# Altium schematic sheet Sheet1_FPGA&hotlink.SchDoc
size A3
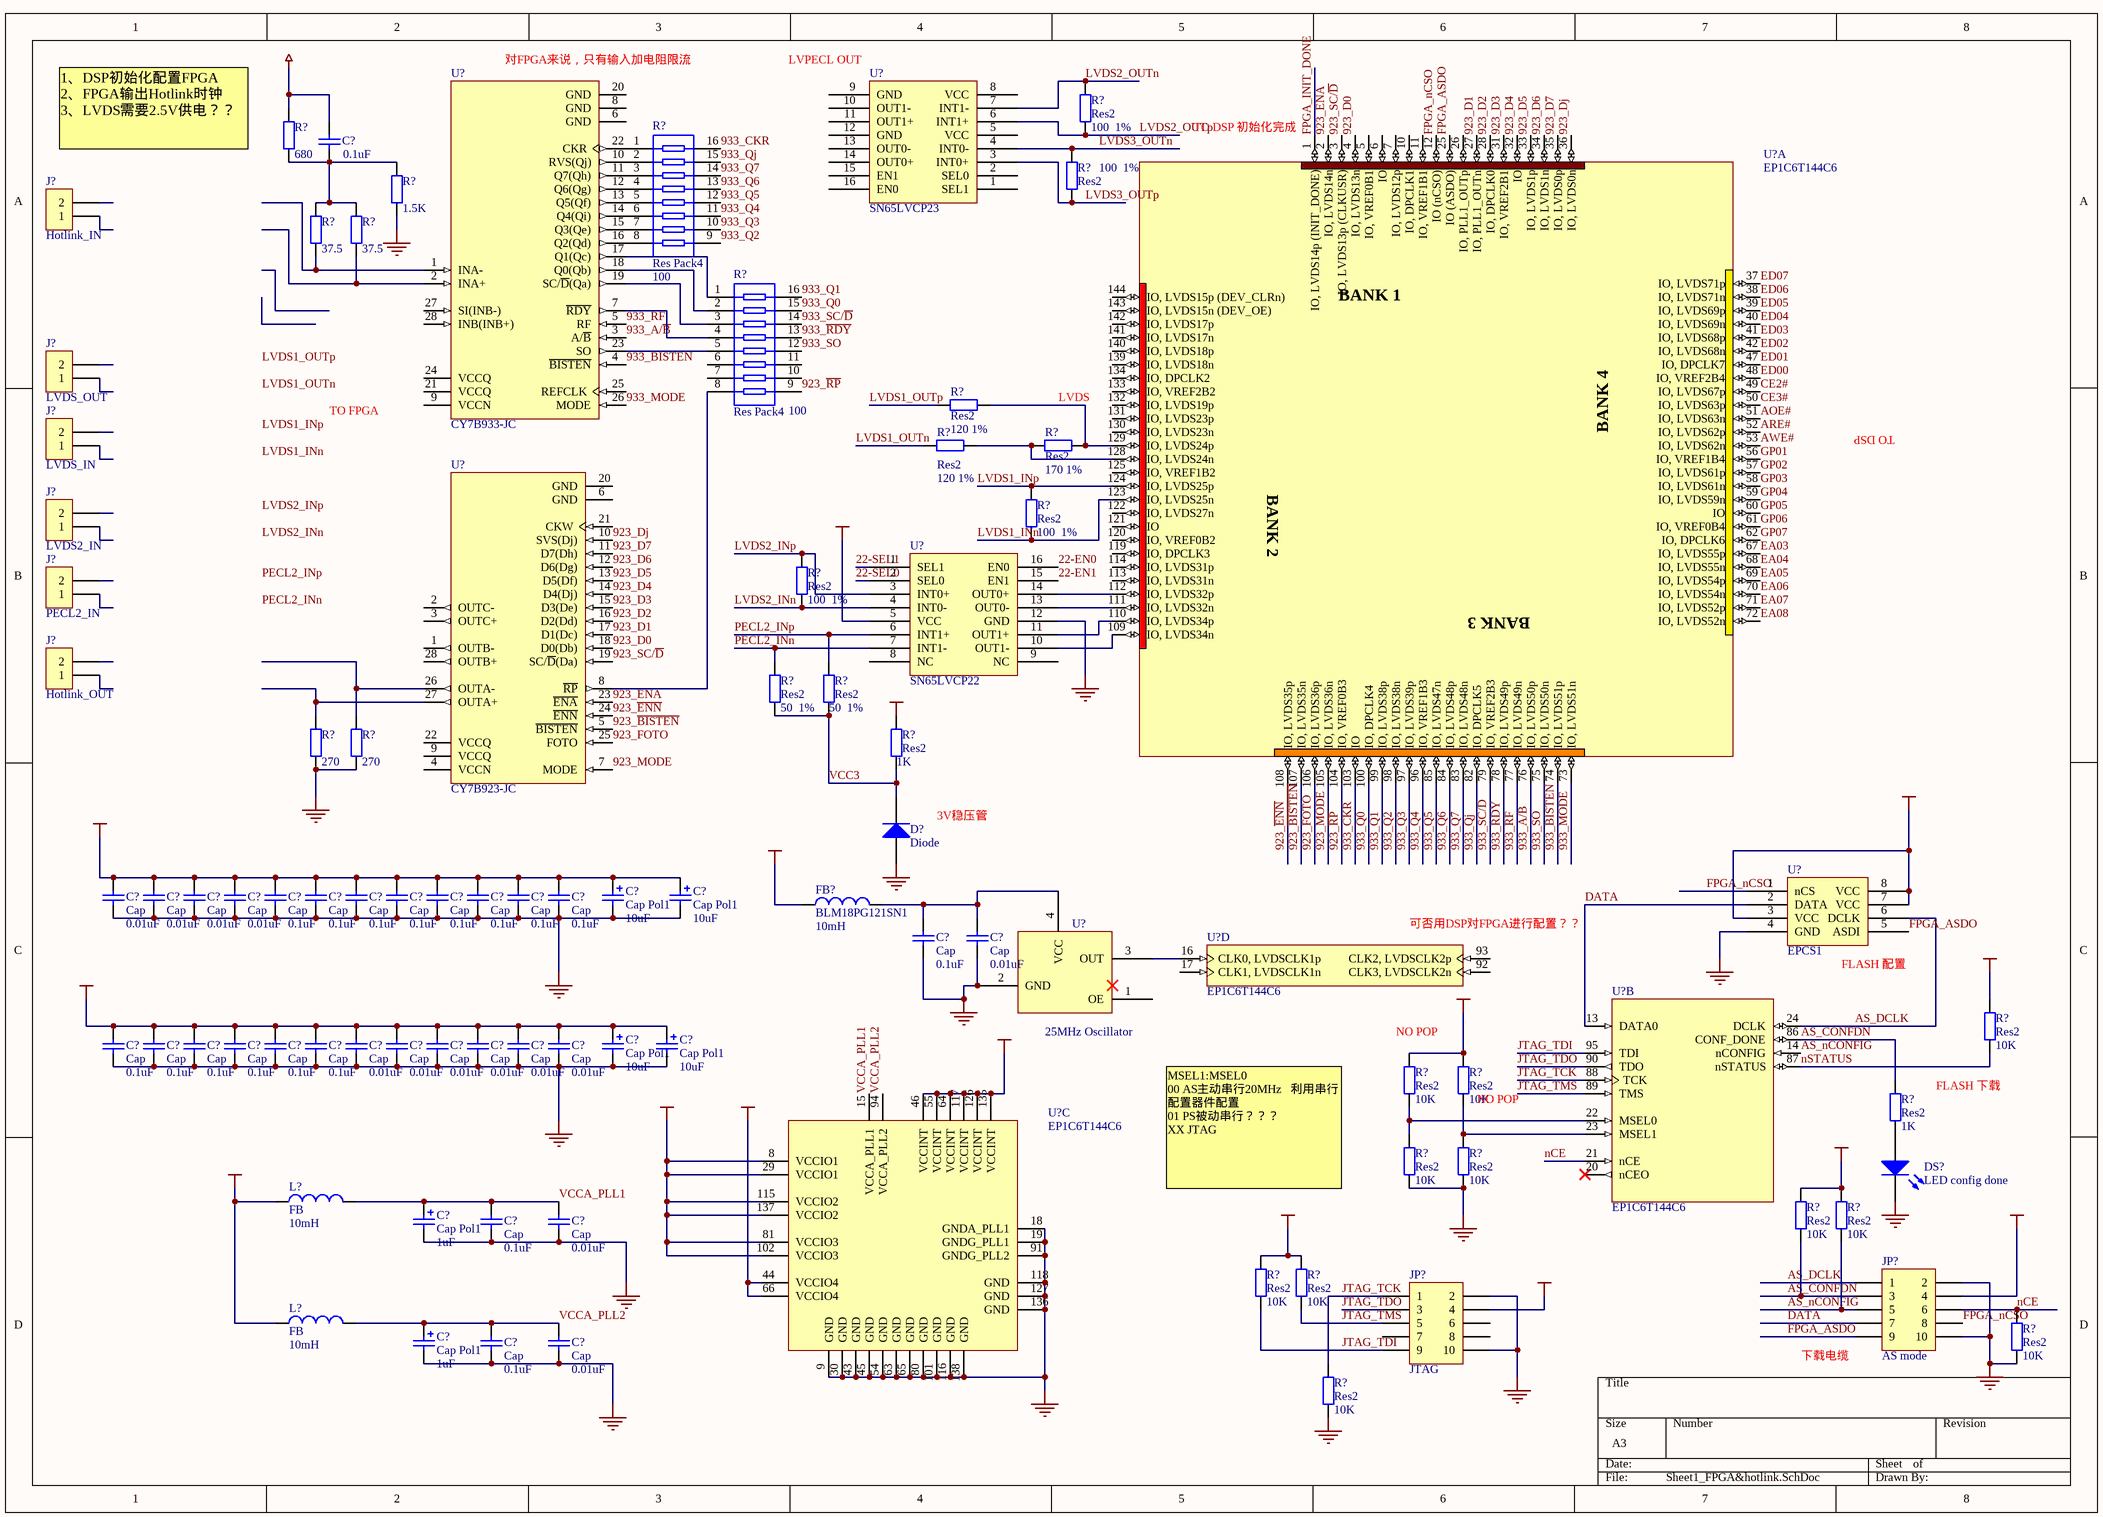
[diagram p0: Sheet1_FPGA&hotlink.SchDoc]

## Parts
(Parts that share a designator on the sheet are numbered #1, #2 ... from top to bottom, then left to right.)
C?#1  value 0.1uF  [RAD-0.3]
C?#2  Cap Pol1  value 10uF  [CC3216-1206]
C?#3  Cap Pol1  value 10uF  [CC3216-1206]
C?#4  Cap  value 0.01uF  [C1608-0603]
C?#5  Cap  value 0.01uF  [C1608-0603]
C?#6  Cap  value 0.01uF  [C1608-0603]
C?#7  Cap  value 0.01uF  [C1608-0603]
C?#8  Cap  value 0.1uF  [C1608-0603]
C?#9  Cap  value 0.1uF  [C1608-0603]
C?#10  Cap  value 0.1uF  [C1608-0603]
C?#11  Cap  value 0.1uF  [C1608-0603]
C?#12  Cap  value 0.1uF  [C1608-0603]
C?#13  Cap  value 0.1uF  [C1608-0603]
C?#14  Cap  value 0.1uF  [C1608-0603]
C?#15  Cap  value 0.1uF  [C1608-0603]
C?#16  Cap  value 0.1uF  [C1608-0603]
C?#17  Cap  value 0.01uF  [C1608-0603]
C?#18  Cap Pol1  value 10uF  [CC3216-1206]
C?#19  Cap Pol1  value 10uF  [CC3216-1206]
C?#20  Cap  value 0.1uF  [C1608-0603]
C?#21  Cap  value 0.1uF  [C1608-0603]
C?#22  Cap  value 0.1uF  [C1608-0603]
C?#23  Cap  value 0.1uF  [C1608-0603]
C?#24  Cap  value 0.1uF  [C1608-0603]
C?#25  Cap  value 0.1uF  [C1608-0603]
C?#26  Cap  value 0.01uF  [C1608-0603]
C?#27  Cap  value 0.01uF  [C1608-0603]
C?#28  Cap  value 0.01uF  [C1608-0603]
C?#29  Cap  value 0.01uF  [C1608-0603]
C?#30  Cap  value 0.01uF  [C1608-0603]
C?#31  Cap  value 0.01uF  [C1608-0603]
C?#32  Cap Pol1  value 1uF  [C1608-0603]
C?#33  Cap  value 0.1uF  [C1608-0603]
C?#34  Cap  value 0.01uF  [C1608-0603]
C?#35  Cap Pol1  value 1uF  [C1608-0603]
C?#36  Cap  value 0.1uF  [C1608-0603]
C?#37  Cap  value 0.01uF  [C1608-0603]
D?  Diode  [DSO-C2/X3.3]
DS?  LED config done  [SMD _LED]
FB?  BLM18PG121SN1  value 10mH  [C1608-0603]
J?#1  Hotlink_IN  [SMA]
J?#2  LVDS_OUT  [SMA]
J?#3  LVDS_IN  [SMA]
J?#4  LVDS2_IN  [SMA]
J?#5  PECL2_IN  [SMA]
J?#6  Hotlink_OUT  [SMA]
JP?#1  AS mode  [HDR2X5]
JP?#2  JTAG  [HDR2X5]
L?#1  FB  value 10mH  [C1608-0603]
L?#2  FB  value 10mH  [C1608-0603]
R?#1  680  [CR1608-0603]
R?#2  Res2  value 100  1%  [CR1608-0603]
R?#3  Res Pack4  value 100  [SSO-G16/X.4]
R?#4  1.5K  [CR1608-0603]
R?#5  Res2  value 100  1%  [CR1608-0603]
R?#6  value 37.5  [CR1608-0603]  (hidden comment: 1.5K)
R?#7  value 37.5  [CR1608-0603]  (hidden comment: 1.5K)
R?#8  Res Pack4  value 100  [SSO-G16/X.4]
R?#9  Res2  value 120 1%  [CR1608-0603]
R?#10  Res2  value 120 1%  [CR1608-0603]
R?#11  Res2  value 170 1%  [CR1608-0603]
R?#12  Res2  value 100  1%  [CR1608-0603]
R?#13  Res2  value 100  1%  [CR1608-0603]
R?#14  Res2  value 50  1%  [CR1608-0603]
R?#15  Res2  value 50  1%  [CR1608-0603]
R?#16  value 270  [CR1608-0603]  (hidden comment: 1.5K)
R?#17  value 270  [CR1608-0603]  (hidden comment: 1.5K)
R?#18  Res2  value 1K  [CR1608-0603]
R?#19  Res2  value 10K  [CR1608-0603]
R?#20  Res2  value 10K  [CR1608-0603]
R?#21  Res2  value 10K  [CR1608-0603]
R?#22  Res2  value 1K  [CR1608-0603]
R?#23  Res2  value 10K  [CR1608-0603]
R?#24  Res2  value 10K  [CR1608-0603]
R?#25  Res2  value 10K  [CR1608-0603]
R?#26  Res2  value 10K  [CR1608-0603]
R?#27  Res2  value 10K  [CR1608-0603]
R?#28  Res2  value 10K  [CR1608-0603]
R?#29  Res2  value 10K  [CR1608-0603]
R?#30  Res2  value 10K  [CR1608-0603]
U?#1  SN65LVCP23
U?#2  CY7B933-JC  [J64]
U?#3  SN65LVCP22  [Model Name]
U?#4  EP1C6T144C6  [TQFP144]  (part A of 4)
U?#5  CY7B923-JC  [J64]
U?#6  EPCS1  [SO-G8]
U?#7  25MHz Oscillator  [OSC50MHz]
U?#8  EP1C6T144C6  [TQFP144]  (part D of 4)
U?#9  EP1C6T144C6  [TQFP144]  (part B of 4)
U?#10  EP1C6T144C6  [TQFP144]  (part C of 4)

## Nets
+5V: C?#1.2 R?#1.1
GND: C?#2.2 C?#3.2 C?#4.1 C?#5.1 C?#6.1 C?#7.1 C?#8.1 C?#9.1 C?#10.1 C?#11.1 C?#12.1 C?#13.1 C?#14.1 C?#15.1 C?#16.1 C?#17.1 C?#18.2 C?#19.2 C?#20.1 C?#21.1 C?#22.1 C?#23.1 C?#24.1 C?#25.1 C?#26.1 C?#27.1 C?#28.1 C?#29.1 C?#30.1 C?#31.1 C?#32.2 C?#33.1 C?#34.1 C?#35.2 C?#36.1 C?#37.1 D?.1(A) DS?.2(K) JP?#1.2 JP?#1.10 JP?#2.2 JP?#2.10 R?#4.2 R?#16.2 R?#17.2 R?#23.1 R?#24.1 R?#29.1 R?#30.1 U?#3.12(GND) U?#6.4(GND) U?#7.2(GND) U?#10.9(GND) U?#10.18(GNDA_PLL1) U?#10.19(GNDG_PLL1) U?#10.30(GND) U?#10.43(GND) U?#10.45(GND) U?#10.54(GND) U?#10.63(GND) U?#10.65(GND) U?#10.80(GND) U?#10.91(GNDG_PLL2) U?#10.101(GND) U?#10.116(GND) U?#10.118(GND) U?#10.127(GND) U?#10.136(GND) U?#10.138(GND)
V3.3: FB?.1
VCC1.5: C?#18.1 C?#19.1 C?#20.2 C?#21.2 C?#22.2 C?#23.2 C?#24.2 C?#25.2 C?#26.2 C?#27.2 C?#28.2 C?#29.2 C?#30.2 C?#31.2 L?#1.1 L?#2.1 U?#10.46(VCCINT) U?#10.55(VCCINT) U?#10.64(VCCINT) U?#10.117(VCCINT) U?#10.126(VCCINT) U?#10.135(VCCINT)
VCC2.5: U?#10.44(VCCIO4) U?#10.66(VCCIO4)
VCC3.3: C?#2.1 C?#3.1 C?#4.2 C?#5.2 C?#6.2 C?#7.2 C?#8.2 C?#9.2 C?#10.2 C?#11.2 C?#12.2 C?#13.2 C?#14.2 C?#15.2 JP?#1.4 JP?#2.4 R?#19.2 R?#20.2 R?#21.2 R?#25.2 R?#26.2 R?#27.2 R?#28.2 U?#3.5(VCC) U?#6.3(VCC) U?#6.7(VCC) U?#6.8(VCC) U?#10.8(VCCIO1) U?#10.29(VCCIO1) U?#10.81(VCCIO3) U?#10.102(VCCIO3) U?#10.115(VCCIO2) U?#10.137(VCCIO2)
VCC5: R?#18.1
22-EN0: U?#3.16(EN0)
22-EN1: U?#3.15(EN1)
22-SEL0: U?#3.2(SEL0)
22-SEL1: U?#3.1(SEL1)
923_~{BISTEN}: U?#4.107(IO,_LVDS35n) U?#5.5(~{BISTEN})
923_D0: U?#4.4(IO,_LVDS13n) U?#5.18(D0(Db))
923_D1: U?#4.27(IO,_PLL1_OUTn) U?#5.17(D1(Dc))
923_D2: U?#4.28(IO,_DPCLK0) U?#5.16(D2(Dd))
923_D3: U?#4.31(IO,_VREF2B1) U?#5.15(D3(De))
923_D4: U?#4.32(IO) U?#5.14(D4(Dj))
923_D5: U?#4.33(IO,_LVDS1p) U?#5.13(D5(Df))
923_D6: U?#4.34(IO,_LVDS1n) U?#5.12(D6(Dg))
923_D7: U?#4.35(IO,_LVDS0p) U?#5.11(D7(Dh))
923_Dj: U?#4.36(IO,_LVDS0n) U?#5.10(SVS(Dj))
923_~{ENA}: U?#4.2(IO,_LVDS14n) U?#5.23(~{ENA})
923_~{ENN}: U?#4.108(IO,_LVDS35p) U?#5.24(~{ENN})
923_FOTO: U?#4.106(IO,_LVDS36p) U?#5.25(FOTO)
923_MODE: U?#4.105(IO,_LVDS36n) U?#5.7(MODE)
923_~{RP}: R?#8.9 U?#4.104(IO,_VREF0B3)
923_SC/~{D}: U?#4.3(IO,_LVDS13p_(CLKUSR)) U?#5.19(SC/~{D}(Da))
933_A/~{B}: U?#2.3(A/~{B}) U?#4.76(IO,_LVDS50p)
933_~{BISTEN}: U?#2.4(~{BISTEN}) U?#4.74(IO,_LVDS51p)
933_CKR: R?#3.16 U?#4.103(IO)
933_MODE: U?#2.26(MODE) U?#4.73(IO,_LVDS51n)
933_Q0: R?#8.15 U?#4.100(IO,_DPCLK4)
933_Q1: R?#8.16 U?#4.99(IO,_LVDS38p)
933_Q2: R?#3.9 U?#4.98(IO,_LVDS38n)
933_Q3: R?#3.10 U?#4.97(IO,_LVDS39p)
933_Q4: R?#3.11 U?#4.96(IO,_VREF1B3)
933_Q5: R?#3.12 U?#4.85(IO,_LVDS47n)
933_Q6: R?#3.13 U?#4.84(IO,_LVDS48p)
933_Q7: R?#3.14 U?#4.83(IO,_LVDS48n)
933_Qj: R?#3.15 U?#4.82(IO,_DPCLK5)
933_~{RDY}: R?#8.13 U?#4.78(IO,_LVDS49p)
933_RF: U?#2.5(RF) U?#4.77(IO,_LVDS49n)
933_SC/~{D}: R?#8.14 U?#4.79(IO,_VREF2B3)
933_SO: R?#8.12 U?#4.75(IO,_LVDS50n)
AOE#: U?#4.51(IO,_LVDS63n)
ARE#: U?#4.52(IO,_LVDS62p)
AS_CONFDN: JP?#1.3 R?#22.2 R?#25.1 U?#9.86(CONF_DONE)
AS_DCLK: JP?#1.1 U?#6.6(DCLK) U?#9.24(DCLK)
AS_nCONFIG: JP?#1.5 R?#26.1 U?#9.14(nCONFIG)
AWE#: U?#4.53(IO,_LVDS62n)
CE2#: U?#4.49(IO,_LVDS67p)
CE3#: U?#4.50(IO,_LVDS63p)
DATA: JP?#1.7 U?#6.2(DATA) U?#9.13(DATA0)
EA03: U?#4.67(IO,_LVDS55p)
EA04: U?#4.68(IO,_LVDS55n)
EA05: U?#4.69(IO,_LVDS54p)
EA06: U?#4.70(IO,_LVDS54n)
EA07: U?#4.71(IO,_LVDS52p)
EA08: U?#4.72(IO,_LVDS52n)
ED00: U?#4.48(IO,_VREF2B4)
ED01: U?#4.47(IO,_DPCLK7)
ED02: U?#4.42(IO,_LVDS68n)
ED03: U?#4.41(IO,_LVDS68p)
ED04: U?#4.40(IO,_LVDS69n)
ED05: U?#4.39(IO,_LVDS69p)
ED06: U?#4.38(IO,_LVDS71n)
ED07: U?#4.37(IO,_LVDS71p)
FPGA_ASDO: JP?#1.9 U?#4.25(IO_(ASDO)) U?#6.5(ASDI)
FPGA_INIT_DONE: U?#4.1(IO,_LVDS14p_(INIT_DONE))
FPGA_nCSO: JP?#1.8 U?#4.12(IO_(nCSO)) U?#6.1(nCS)
GP01: U?#4.56(IO,_VREF1B4)
GP02: U?#4.57(IO,_LVDS61p)
GP03: U?#4.58(IO,_LVDS61n)
GP04: U?#4.59(IO,_LVDS59n)
GP05: U?#4.60(IO)
GP06: U?#4.61(IO,_VREF0B4)
GP07: U?#4.62(IO,_DPCLK6)
JTAG_TCK: JP?#2.1 R?#30.2 U?#9.88(TCK)
JTAG_TDI: JP?#2.9 R?#27.1 U?#9.95(TDI)
JTAG_TDO: JP?#2.3 U?#9.90(TDO)
JTAG_TMS: JP?#2.5 R?#28.1 U?#9.89(TMS)
LVDS1_INn: R?#12.2 U?#4.123(IO,_LVDS25n)
LVDS1_INp: R?#12.1 U?#4.124(IO,_LVDS25p)
LVDS1_OUTn: R?#10.1
LVDS1_OUTp: R?#9.1
LVDS2_INn: R?#13.2 U?#3.4(INT0-)
LVDS2_INp: R?#13.1 U?#3.3(INT0+)
LVDS2_OUTn: R?#2.2 U?#1.7(INT1-)
LVDS2_OUTp: R?#2.1 U?#1.6(INT1+)
LVDS3_OUTn: R?#5.2 U?#1.4(INT0-)
LVDS3_OUTp: R?#5.1 U?#1.3(INT0+)
nCE: JP?#1.6 R?#29.2 U?#9.21(nCE)
nSTATUS: R?#19.1 U?#9.87(nSTATUS)
PECL2_INn: R?#14.1 U?#3.7(INT1-)
PECL2_INp: R?#15.1 U?#3.6(INT1+)
VCC3: D?.2(K) R?#14.2 R?#15.2 R?#18.2
VCCA_PLL1: C?#32.1 C?#33.2 C?#34.2 L?#1.2 U?#10.15(VCCA_PLL1)
VCCA_PLL2: C?#35.1 C?#36.2 C?#37.2 L?#2.2 U?#10.94(VCCA_PLL2)
NetC?#1_1: C?#1.1 R?#1.2 R?#4.1 R?#6.1 R?#7.1
NetC?#16_2: C?#16.2 C?#17.2 FB?.2 U?#7.4(VCC)
NetDS?_1: DS?.1(A) R?#22.1
NetR?#3_1: R?#3.1 U?#2.22(CKR)
NetR?#3_2: R?#3.2 U?#2.10(RVS(Qj))
NetR?#3_3: R?#3.3 U?#2.11(Q7(Qh))
NetR?#3_4: R?#3.4 U?#2.12(Q6(Qg))
NetR?#3_5: R?#3.5 U?#2.13(Q5(Qf))
NetR?#3_6: R?#3.6 U?#2.14(Q4(Qi))
NetR?#3_7: R?#3.7 U?#2.15(Q3(Qe))
NetR?#3_8: R?#3.8 U?#2.16(Q2(Qd))
NetR?#6_2: R?#6.2 U?#2.1(INA-)
NetR?#7_2: R?#7.2 U?#2.2(INA+)
NetR?#8_1: R?#8.1 U?#2.17(Q1(Qc))
NetR?#8_2: R?#8.2 U?#2.18(Q0(Qb))
NetR?#8_3: R?#8.3 U?#2.19(SC/~{D}(Qa))
NetR?#8_4: R?#8.4 U?#2.7(~{RDY})
NetR?#8_5: R?#8.5 U?#2.23(SO)
NetR?#8_8: R?#8.8 U?#5.8(~{RP})
NetR?#9_2: R?#9.2 R?#11.1 U?#4.129(IO,_LVDS24p)
NetR?#10_2: R?#10.2 R?#11.2 U?#4.128(IO,_LVDS24n)
NetR?#16_1: R?#16.1 U?#5.27(OUTA+)
NetR?#17_1: R?#17.1 U?#5.26(OUTA-)
NetR?#20_1: R?#20.1 R?#23.2 U?#9.22(MSEL0)
NetR?#21_1: R?#21.1 R?#24.2 U?#9.23(MSEL1)
NetU?#3_10: U?#3.10(OUT1-) U?#4.109(IO,_LVDS34n)
NetU?#3_11: U?#3.11(OUT1+) U?#4.110(IO,_LVDS34p)
NetU?#3_13: U?#3.13(OUT0-) U?#4.111(IO,_LVDS32n)
NetU?#3_14: U?#3.14(OUT0+) U?#4.112(IO,_LVDS32p)
NetU?#7_3: U?#7.3(OUT) U?#8.16(CLK0,_LVDSCLK1p)

Not connected (* = marked no-connect by the designer): J?#1 1 2; J?#2 1 2; J?#3 1 2; J?#4 1 2; J?#5 1 2; J?#6 1 2; JP?#2 6 7 8; R?#8 6 7 10 11; U?#1 1(SEL1) 2(SEL0) 5(VCC) 8(VCC) 9(GND) 10(OUT1-) 11(OUT1+) 12(GND) 13(OUT0-) 14(OUT0+) 15(EN1) 16(EN0); U?#2 6(GND) 8(GND) 9(VCCN) 20(GND) 21(VCCQ) 24(VCCQ) 25(REFCLK) 27(SI(INB-)) 28(INB(INB+)); U?#3 8(NC) 9(NC); U?#4 5(IO,_VREF0B1) 6(IO) 7(IO,_LVDS12p) 10(IO,_DPCLK1) 11(IO,_VREF1B1) 26(IO,_PLL1_OUTp) 113(IO,_LVDS31n) 114(IO,_LVDS31p) 119(IO,_DPCLK3) 120(IO,_VREF0B2) 121(IO) 122(IO,_LVDS27n) 125(IO,_VREF1B2) 130(IO,_LVDS23n) 131(IO,_LVDS23p) 132(IO,_LVDS19p) 133(IO,_VREF2B2) 134(IO,_DPCLK2) 139(IO,_LVDS18n) 140(IO,_LVDS18p) 141(IO,_LVDS17n) 142(IO,_LVDS17p) 143(IO,_LVDS15n_(DEV_OE)) 144(IO,_LVDS15p_(DEV_CLRn)); U?#5 1(OUTB-) 2(OUTC-) 3(OUTC+) 4(VCCN) 6(GND) 9(VCCQ) 20(GND) 21(CKW) 22(VCCQ) 28(OUTB+); U?#7 1(OE); U?#8 17(CLK1,_LVDSCLK1n) 92(CLK3,_LVDSCLK2n) 93(CLK2,_LVDSCLK2p); U?#9 20(nCEO)*

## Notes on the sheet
- (near U?#2) 对FPGA来说，只有输入加电阻限流
- (near U?#1) LVPECL OUT
- 1、DSP初始化配置FPGA
  2、FPGA输出Hotlink时钟
  3、LVDS需要2.5V供电？？
- (near U?#4) TO DSP 初始化完成
- TO FPGA
- LVDS
- TO DSP
- (near D?) 3V稳压管
- (near U?#8) 可否用DSP对FPGA进行配置？？
- (near U?#6) FLASH 配置
- (near R?#20) NO POP
- (near R?#21) NO POP
- (near R?#22) FLASH 下载
- MSEL1:MSEL0
  00 AS主动串行20MHz   利用串行配置器件配置
  01 PS被动串行？？？
  XX JTAG
- 下载电缆
- Labels drawn without touching a wire or pin: LVDS1_INn, LVDS1_INp, LVDS1_OUTn, LVDS1_OUTp, LVDS2_INn, LVDS2_INp, PECL2_INn, PECL2_INp

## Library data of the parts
C?#1 C?#4-C?#17 C?#20-C?#31 C?#33 C?#34 C?#36 C?#37 = Cap: Capacitor
C?#2 C?#3 C?#18 C?#19 C?#32 C?#35 = Cap Pol1: Polarized Capacitor (Radial)
D? = Diode: Default Diode; Code - JEDEC: DO-214-AB
DS? = LED3: Typical BLUE SiC LED; Revision 1: Jul-2002: Re-released for DXP Platform.; Revision 2: 17-Dec-2003: PCB Footprint replaced.
FB? L?#1 L?#2 = Inductor
J?#1-J?#6 = CON2: Hotlink接口
JP?#1 JP?#2 = Header 5X2: Header, 5-Pin, Dual row
R?#1 R?#2 R?#4-R?#7 R?#9-R?#30 = Res2: Resistor
R?#3 R?#8 = Res Pack4: Resistor Array; Code - JEDEC: MO-150-AC
U?#2 = CY7B933-JC: HOTLink Receiver; Package Information: Latest Revision: Jul-2000; Code - IPC: PLCC-28
U?#4 U?#8-U?#10 = EP1C6T144C6: Cyclone Family, 1.5V FPGA, 98 I/O Pins, 2 x PLLs, Commercial Grade, Speed Grade 6; Package Information: Latest Revision: ver11.0, Feb-2003; Code - JEDEC: MS-026-BFB; Code - IPC: SQFP20X20-144
U?#5 = CY7B923-JC: HOTLink Transmitter; Package Information: Latest Revision: Jul-2000; Code - IPC: PLCC-28
U?#7 = Oscillator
